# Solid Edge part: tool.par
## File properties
Author: Blackblade
Template: Normal.par
Last saved by: Blackblade
Revision: 6
Application: Solid Edge
Accuracy: 0.990
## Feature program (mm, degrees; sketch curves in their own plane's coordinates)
lofted protrusion "unnamed LoftedProtrusion 1"
sketch for "ExtrudedProtrusion_4" plane through (0, 0, 0) normal (0, 0, 1) x-axis (1, 0, 0)
extrude "ExtrudedProtrusion_4" add finite 2 along -normal
sketch used by "jalg" plane through (18.9581, 0, -2) normal (0, 0, -1) x-axis (1, 0, 0)
extrude "jalg" add finite 10 along +normal
sketch used by "ExtrudedProtrusion_7" plane through (18.9581, 0, -12) normal (0, 0, -1) x-axis (1, 0, 0)
extrude "ExtrudedProtrusion_7" add finite 1 along +normal
chamfer "Chamfer_2" setback 0.5
fillet "Round_5" radius 1
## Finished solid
Body 1: solid body, 15 faces, 30 edges, 18 vertices.
  Faces by surface: plane 7, cylinder 3, blend 2, spline 2, cone 1
  Edges by curve: intersection 16, circle 11, spline 2, line 1
Bounding box of the edges (mm; curved faces can reach further): 31.458 x 38.793 x 54.000, from (0, -19.3469, -13) to (31.4581, 19.4464, 41).
Cylindrical faces by radius (mm): R1 x1, R8.3603 x1, R12.5 x1
Conical faces (half-angle, radius in mm at the cone's reference point): 45 deg R12 x1
Planar faces by outward normal: +x 1, +z 4, -z 2
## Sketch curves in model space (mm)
circle centre (18.9581, 0, 0) radius 8.3603
arc centre (2.3845, -15, 41) radius 2.3845 from (4.1764, -13.4268, 41) through (3.0231, -17.2974, 41) to (0, -15, 41)
arc centre (34.2398, -1.0349, 41) radius 32.5172 from (3.9308, 10.7436, 41) through (1.7243, -1.3652, 41) to (4.1764, -13.4268, 41)
arc centre (2.3845, 12.5588, 41) radius 2.3845 from (0, 12.5588, 41) through (3.4484, 14.6927, 41) to (3.9308, 10.7436, 41)
line (0, 12.5588, 41) -> (0, -15, 41)
arc centre (4.9823, -15, 40) radius 4.9823 from (6.2063, -10.1704, 40) through (7.9238, -19.0213, 40) to (0, -15, 40)
arc centre (37.0712, 0.0634, 40) radius 32.5172 from (5.9504, 9.4903, 40) through (4.5567, -0.3598, 40) to (6.2063, -10.1704, 40)
arc centre (4.9823, 14.3777, 40) radius 4.9823 from (0, 14.3777, 40) through (8.1446, 18.2278, 40) to (5.9504, 9.4903, 40)
line (0, 14.3777, 40) -> (0, -15, 40)
arc centre (3.3384, -15, 30) radius 3.3384 from (5.3824, -12.3605, 30) through (4.8083, -17.9974, 30) to (0, -15, 30)
arc centre (35.6424, -0.4566, 30) radius 32.5172 from (6.091, 13.111, 30) through (3.1378, 0.4475, 30) to (5.3824, -12.3605, 30)
arc centre (3.3384, 15, 30) radius 3.3384 from (0, 15, 30) through (4.4215, 18.1578, 30) to (6.091, 13.111, 30)
line (0, 15, 30) -> (0, -15, 30)
arc centre (4.0387, -15, 20) radius 4.0387 from (5.924, -11.4283, 20) through (6.0202, -18.5192, 20) to (0, -15, 20)
arc centre (36.4267, -0.1608, 20) radius 32.5172 from (6.0401, 11.4163, 20) through (3.9099, 0.0045, 20) to (5.924, -11.4283, 20)
arc centre (4.0387, 14.9242, 20) radius 4.0387 from (0, 14.9242, 20) through (6.2725, 18.289, 20) to (6.0401, 11.4163, 20)
line (0, 14.9242, 20) -> (0, -15, 20)
arc centre (4.286, -15, 10) radius 4.286 from (6.2774, -11.2048, 10) through (6.3933, -18.7322, 10) to (0, -15, 10)
arc centre (36.8032, 0, 10) radius 32.5172 from (6.2774, 11.2048, 10) through (4.286, 0, 10) to (6.2774, -11.2048, 10)
arc centre (4.286, 15, 10) radius 4.286 from (0, 15, 10) through (6.6117, 18.6001, 10) to (6.2774, 11.2048, 10)
line (0, 15, 10) -> (0, -15, 10)
arc centre (11, 15.2449, 4.7758) radius 4.7758 from (11, 10.7683, 6.4397) through (11, 19.3943, 7.1403) to (11, 15.2449, 0)
arc centre (11, -0.1005, 37.0867) radius 32.5172 from (11, -10.1885, 6.1738) through (11, 0.3119, 4.572) to (11, 10.7683, 6.4397)
arc centre (11, -14.7551, 4.7758) radius 4.7758 from (11, -14.7551, 0) through (11, -18.4185, 7.8398) to (11, -10.1885, 6.1738)
line (11, -14.7551, 0) -> (11, 15.2449, 0)
arc centre (21, 15.4898, 5.2656) radius 5.2656 from (21, 10.3651, 6.4757) through (21, 19.7147, 8.4085) to (21, 15.4898, 0)
arc centre (21, -0.1511, 37.2455) radius 32.5172 from (21, -9.3021, 6.0424) through (21, 0.565, 4.7361) to (21, 10.3651, 6.4757)
arc centre (21, -14.5102, 5.2656) radius 5.2656 from (21, -14.5102, 0) through (21, -18.1777, 9.044) to (21, -9.3021, 6.0424)
line (21, -14.5102, 0) -> (21, 15.4898, 0)
circle centre (18.9581, 0, -2) radius 1
circle centre (18.9581, 0, -12) radius 12.5
arc centre (31, 15, 4.286) radius 4.286 from (31, 11.2048, 6.2774) through (31, 18.7322, 6.3933) to (31, 15, 0)
arc centre (31, 0, 36.8032) radius 32.5172 from (31, -11.2048, 6.2774) through (31, 0, 4.286) to (31, 11.2048, 6.2774)
arc centre (31, -15, 4.286) radius 4.286 from (31, -15, 0) through (31, -18.6001, 6.6117) to (31, -11.2048, 6.2774)
line (31, -15, 0) -> (31, 15, 0)
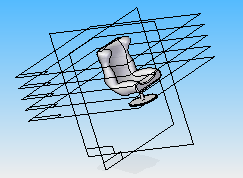
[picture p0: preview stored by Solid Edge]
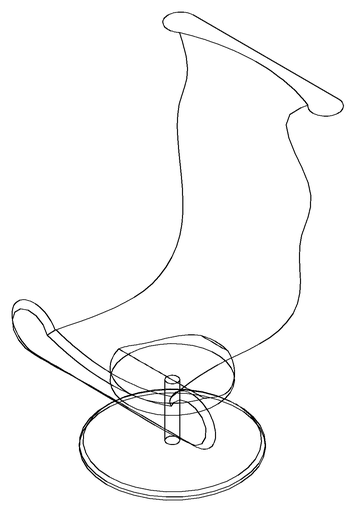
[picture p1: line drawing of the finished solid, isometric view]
